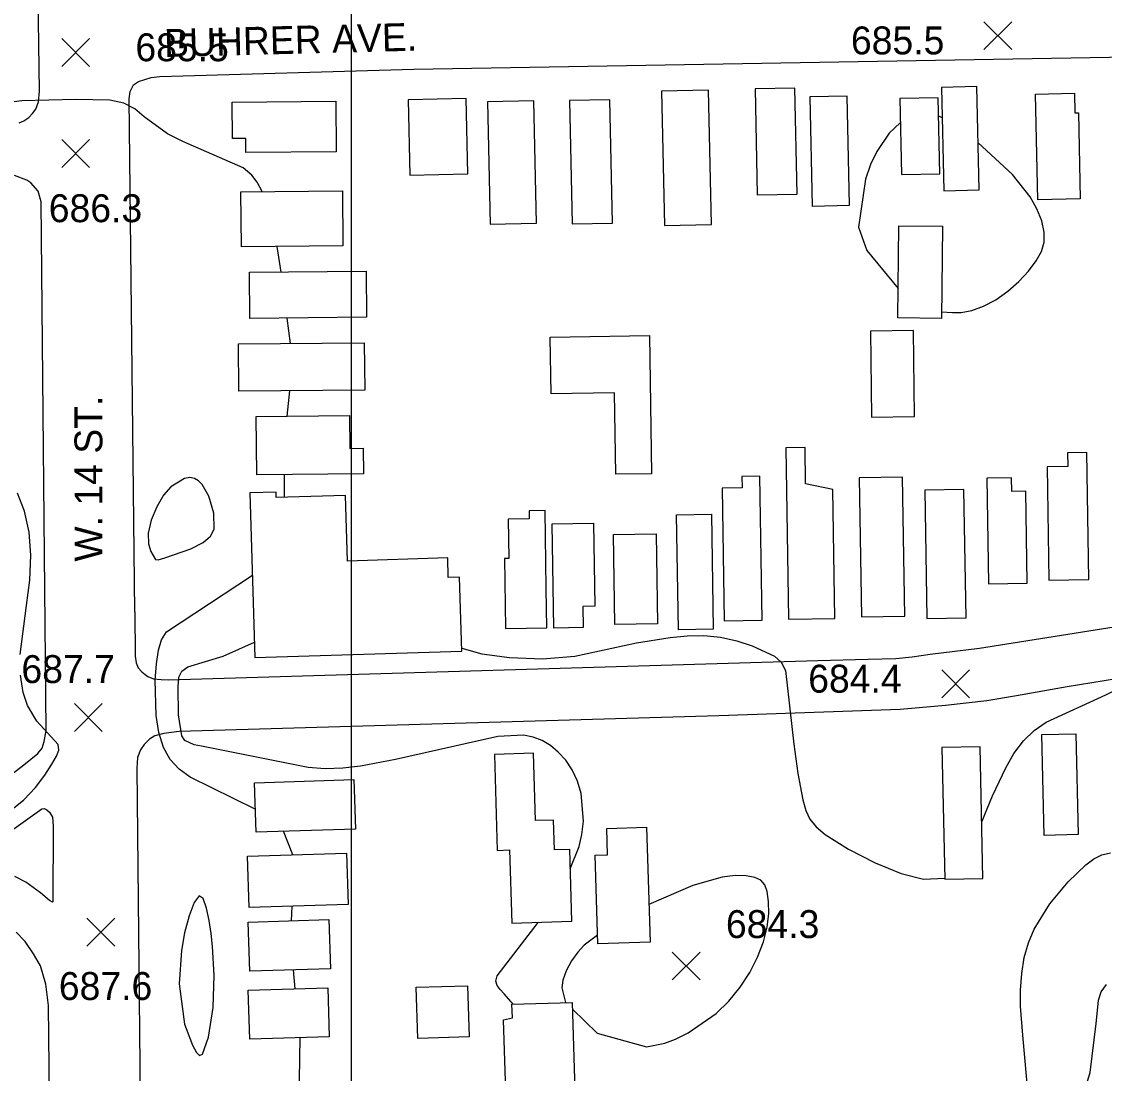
# Model space of a CAD drawing. Extents: x 79600 to 91800, y 75600 to 84400.
# Drawn here: x 86823 to 87405, y 77429 to 77994 of the extents above; entities that cross this region are included whole.
import ezdxf

# ---------------------------------------------------------------- set-up
doc = ezdxf.new("R2010")
doc.units = 0
for name, color, linetype in [('080-090$0$BLDG', 7, 'Continuous'), ('080-090$0$GRID', 7, 'Continuous'), ('080-090$0$INDEX', 7, 'Continuous'), ('080-090$0$INTER', 7, 'Continuous'), ('080-090$0$ROAD', 7, 'Continuous'), ('080-090$0$ROAD-NAME', 7, 'Continuous'), ('080-090$0$SPOTMARK', 7, 'Continuous'), ('080-090$0$SPOTS', 7, 'Continuous')]:
    doc.layers.add(name, color=color, linetype=linetype)

# ---------------------------------------------------------------- blocks, each defined once
blk = doc.blocks.new('080-090$0$SPOTS')
at = {"layer": '080-090$0$SPOTMARK'}
for p, q in [((-0.5, -0.5), (0.5, 0.5)), ((-0.5, 0.5), (0.5, -0.5))]:
    blk.add_line(p, q, dxfattribs=at)

msp = doc.modelspace()

# ---------------------------------------------------------------- linework, layer by layer
at = {"layer": '080-090$0$BLDG'}
for points in [[(87166.82, 77956.92), (87168.39, 77884.81), (87193.69, 77885.37), (87192.11, 77957.47)], [(87217.06, 77958.12), (87218.31, 77901.17), (87239.72, 77901.64), (87238.47, 77958.59)], [(87246.43, 77953.81), (87247.72, 77895.19), (87267.85, 77895.63), (87266.57, 77954.25)], [(87317.23, 77958.97), (87318.44, 77903.42), (87337.53, 77903.84), (87336.32, 77959.39)], [(87388.87, 77945.27), (87390.82, 77945.31), (87391.84, 77899), (87368.93, 77898.49), (87367.69, 77955.34), (87388.63, 77955.8)], [(86992.04, 77924.34), (86943.5, 77923.9), (86943.43, 77931.56), (86936.32, 77931.49), (86936.14, 77951.1), (86991.79, 77951.62)], [(87030.77, 77952.35), (87031.66, 77911.84), (87062.69, 77912.52), (87061.8, 77953.03)], [(87073.28, 77951.17), (87074.72, 77885.44), (87099.62, 77885.98), (87098.18, 77951.72)], [(87117.43, 77951.83), (87118.88, 77885.61), (87140.55, 77886.08), (87139.1, 77952.3)], [(87294.81, 77952.94), (87295.7, 77912.12), (87316.45, 77912.57), (87315.55, 77953.39)], [(86995.7, 77873.87), (86941.13, 77873.36), (86940.85, 77902.84), (86995.42, 77903.35)], [(87293.87, 77835.1), (87294.41, 77884.56), (87317.78, 77884.31), (87317.24, 77834.84)], [(87008.17, 77860.17), (87008.39, 77835.42), (86945.67, 77834.84), (86945.45, 77859.59)], [(87279.07, 77827.94), (87279.72, 77781.83), (87302.82, 77782.16), (87302.17, 77828.26)], [(87007.4, 77796.34), (86939.75, 77795.72), (86939.52, 77821.13), (87007.16, 77821.76)], [(87142.34, 77751.08), (87141.62, 77794.87), (87107.47, 77794.31), (87106.97, 77824.81), (87160.29, 77825.68), (87161.5, 77751.37)], [(86999.32, 77764.99), (87006.53, 77765.06), (87006.66, 77751.33), (86949.34, 77750.8), (86949.05, 77782.12), (86999.16, 77782.58)], [(87244.27, 77745.97), (87243.96, 77765.37), (87233.57, 77765.2), (87235.07, 77673.2), (87259.96, 77673.61), (87258.84, 77742.92)], [(87384.94, 77762.61), (87385.06, 77755.29), (87373.98, 77755.11), (87374.98, 77694.18), (87396.46, 77694.53), (87395.35, 77762.78)], [(87210.02, 77749.94), (87210.13, 77743.73), (87199.36, 77743.55), (87200.52, 77672.34), (87220.91, 77672.67), (87219.65, 77750.1)], [(87272.98, 77749.13), (87274.2, 77674.4), (87297.59, 77674.78), (87296.37, 77749.51)], [(87355.03, 77741.83), (87354.91, 77749.17), (87341.62, 77748.96), (87342.55, 77692.17), (87363.32, 77692.51), (87362.52, 77741.95)], [(87058.3, 77695.79), (87052.28, 77695.61), (87051.96, 77706.07), (86998.06, 77704.41), (86996.98, 77739.73), (86959.83, 77738.59), (86959.74, 77741.5), (86945.67, 77741.06), (86948.39, 77652.63), (87059.52, 77656.05)], [(87308.25, 77742.56), (87309.37, 77673.49), (87330.43, 77673.83), (87329.31, 77742.91)], [(87095.7, 77731.4), (87095.77, 77727.13), (87084.39, 77726.94), (87084.74, 77705.78), (87082.43, 77705.74), (87083.04, 77668.14), (87105.28, 77668.51), (87104.94, 77689.65), (87104.93, 77689.67), (87104.25, 77731.54)], [(87175.95, 77667.48), (87174.95, 77729.26), (87193.65, 77729.56), (87194.66, 77667.79)], [(87124.5, 77680.01), (87124.69, 77668.67), (87108.92, 77668.41), (87108.01, 77724.43), (87130.29, 77724.79), (87131.01, 77680.12)], [(87141.75, 77670.37), (87140.97, 77718.76), (87163.94, 77719.13), (87164.73, 77670.74)], [(87389.52, 77611.56), (87390.66, 77557.41), (87372.35, 77557.02), (87371.21, 77611.17)], [(87109.37, 77549.22), (87108.87, 77565.21), (87099.2, 77564.91), (87098.09, 77601.1), (87077.03, 77600.46), (87078.61, 77548.95), (87085.17, 77549.16), (87086.38, 77509.81), (87118.71, 77510.81), (87117.52, 77549.47)], [(87317.51, 77604.16), (87319, 77533.44), (87339.51, 77533.87), (87338.02, 77604.59)], [(87002.35, 77560.38), (86948.96, 77558.73), (86948.14, 77585.31), (87001.53, 77586.95)], [(87160.69, 77499.62), (87132.66, 77498.75), (87131.2, 77546.29), (87137.82, 77546.5), (87137.38, 77560.72), (87158.79, 77561.38)], [(86998.49, 77519.9), (86945.22, 77518.26), (86944.37, 77545.79), (86997.64, 77547.43)], [(86988.96, 77485.32), (86945.62, 77483.98), (86944.8, 77510.42), (86988.15, 77511.75)], [(86988.34, 77448.82), (86945.58, 77447.5), (86944.77, 77473.81), (86987.53, 77475.12)], [(87062.59, 77476.2), (87063.43, 77448.7), (87035.89, 77447.85), (87035.04, 77475.35)], [(87086.7, 77459), (87086.47, 77466.26), (87118.84, 77467.26), (87121.03, 77396.38), (87086.22, 77395.31), (87085.98, 77403.14), (87083.7, 77403.07), (87082.01, 77457.93)]]:
    msp.add_lwpolyline(points, close=True, dxfattribs=at)
at = {"layer": '080-090$0$GRID'}
msp.add_line((87000, 80000), (87000, 76000), dxfattribs=at)
at = {"layer": '080-090$0$INDEX'}
msp.add_lwpolyline([(87394.48, 77420.72), (87397.07, 77429.53), (87400.43, 77455.83), (87400.99, 77462.85), (87401.6, 77468.43), (87402.96, 77472.91), (87405.89, 77476.78)], dxfattribs=at)
at = {"layer": '080-090$0$INTER'}
for p, q in [((87317.59, 77942.56), (87315.77, 77943.55)), ((86962.46, 77859.75), (86960.37, 77873.54)), ((86967.42, 77821.39), (86965.71, 77835.02)), ((86965.76, 77782.27), (86967.22, 77795.97)), ((86964.32, 77738.72), (86964.35, 77750.94)), ((86968.75, 77546.54), (86963.73, 77559.19)), ((86968.11, 77511.14), (86968.43, 77518.98)), ((86969.97, 77474.58), (86969.07, 77484.71))]:
    msp.add_line(p, q, dxfattribs=at)
for points in [[(86952.32, 77902.95), (86949.57, 77908.09), (86946.7, 77911.82), (86942.08, 77915.71), (86909.61, 77929.9), (86901.42, 77934.06), (86888.83, 77943.16), (86883.77, 77947.37), (86877.97, 77950.49), (86870.51, 77952.08), (86852.2, 77952.48), (86823.08, 77951.8), (86776.05, 77945.64)], [(87295.09, 77939.85), (87289.14, 77934.41), (87282.48, 77924.57), (87279.13, 77917.53), (87276.39, 77909.63), (87272.73, 77883.77)], [(87317.28, 77838.38), (87323.17, 77837.91), (87327.86, 77838.04), (87333.54, 77839.06), (87339.85, 77841.37), (87346.43, 77844.88), (87352.89, 77849.38), (87358.87, 77854.61), (87364.07, 77860.19), (87368.2, 77865.69), (87371, 77870.82), (87372.42, 77875.85), (87372.45, 77881.22), (87371.1, 77887.21), (87368.51, 77893.62), (87364.87, 77900.1), (87355.41, 77912.14), (87336.98, 77929.2)], [(87272.73, 77883.77), (87277.16, 77871.32), (87294.05, 77850.91)], [(86822.17, 77654.24), (86825.69, 77680.45), (86827.49, 77694.2), (86828.02, 77707.51), (86827.08, 77719.95), (86824.64, 77731.15), (86820.79, 77740.85)], [(87338.87, 77564.19), (87344.66, 77578.25), (87351.76, 77593.31), (87356.18, 77600.96), (87361.24, 77607.81), (87366.99, 77613.38), (87373.5, 77617.92), (87405.51, 77632.54), (87412.64, 77636.19), (87418.36, 77640.48), (87422.22, 77646), (87425.63, 77660.75), (87428.42, 77668.07), (87433.87, 77674.13), (87485.17, 77701.91)], [(86948.58, 77571.08), (86913.56, 77588.23), (86907.59, 77592.5), (86902.86, 77597.73), (86899.3, 77604.27), (86896.84, 77612.3), (86895.36, 77621.41), (86894.78, 77640.47), (86895.44, 77649.19), (86896.59, 77656.54), (86898.25, 77662.09), (86900.92, 77666.41), (86947.03, 77696.75)], [(87059.47, 77657.61), (87070.27, 77654.62), (87085.14, 77652.57), (87102.91, 77651.83), (87120.19, 77653.28), (87153.45, 77660.47), (87171.49, 77663.35), (87180.53, 77664.24), (87189.53, 77664.44), (87198.5, 77663.6), (87207.37, 77661.56), (87215.58, 77658.79), (87227.6, 77653.25), (87231.12, 77650.12), (87233.38, 77645.52), (87237.99, 77605.96), (87240.15, 77590.33), (87242.71, 77576.03), (87244.3, 77570.44), (87246.54, 77565.75), (87249.91, 77561.53), (87254.71, 77557.43), (87267.36, 77549.5), (87281.54, 77542.28), (87295.61, 77536.57), (87307.57, 77533.43), (87318.99, 77534.04)], [(87117.84, 77539.05), (87122.51, 77550.95), (87124.07, 77557.39), (87124.87, 77564.59), (87123.71, 77579.42), (87121.68, 77586.17), (87118.82, 77592.2), (87115.34, 77597.43), (87111.39, 77601.79), (87107.12, 77605.3), (87102.63, 77607.96), (87097.95, 77609.79), (87092.71, 77610.77), (87078.91, 77610.14), (87023.9, 77597.86), (87005.07, 77594.21), (86995.6, 77593.12), (86986.19, 77592.79), (86976.95, 77593.44), (86919.67, 77604.87), (86915.7, 77605.68), (86910.68, 77607.99), (86909.09, 77610.51), (86907.31, 77621.86), (86907.07, 77636.91), (86907.58, 77641.96), (86909.13, 77645.24), (86912.41, 77647.52), (86931.4, 77653.33), (86948.14, 77660.77)], [(86816.94, 77570.14), (86824.26, 77576.12), (86830.46, 77582.79), (86835.46, 77589.43), (86839.25, 77595.22), (86841.82, 77599.54), (86843, 77602.85), (86842.61, 77605.82), (86831.28, 77618.31), (86826.18, 77626.71), (86823.94, 77633.85), (86822.41, 77643.11)], [(87363.99, 77415.66), (87360.91, 77449.69), (87359.74, 77465.23), (87359.74, 77473.87), (87360.34, 77482.72), (87361.7, 77491.29), (87363.94, 77499.22), (87367.04, 77506.58), (87375.45, 77520.15), (87385.38, 77532.06), (87394.77, 77541.15), (87399.13, 77544.33), (87403.38, 77546.46), (87407.97, 77547.6)], [(87158.85, 77443.28), (87168.55, 77445.29), (87174.3, 77447.41), (87181.2, 77450.82), (87196.15, 77461.22), (87203.01, 77467.92), (87209.1, 77475.36), (87214.28, 77483.31), (87218.47, 77491.53), (87221.59, 77499.75), (87223.59, 77507.69), (87224.44, 77515.07), (87224.36, 77521.55), (87223.59, 77526.76), (87222.29, 77530.46), (87220.21, 77532.9), (87216.97, 77534.43), (87212.31, 77535.31), (87206.37, 77535.43), (87199.35, 77534.57), (87183.67, 77530.05), (87160.07, 77519.94)], [(87087.15, 77466.28), (87082.25, 77471.85), (87080.2, 77474.22), (87078.57, 77476.35), (87077.85, 77478.61), (87078.53, 77481.51), (87100.53, 77510.25)], [(87132.51, 77503.45), (87125.3, 77497.96), (87121.86, 77494.27), (87118.5, 77489.5), (87115.67, 77484.24), (87113.81, 77479.2), (87113.2, 77474.99), (87115.26, 77467.15)], [(87118.96, 77463.6), (87132.31, 77450.77), (87158.85, 77443.28)], [(86959.62, 77368.68), (86968.71, 77397.6), (86972.2, 77414.16), (86972.71, 77448.34)]]:
    msp.add_lwpolyline(points, dxfattribs=at)
for points in [[(86900.04, 77706.15), (86913.87, 77711.07), (86920.5, 77714.33), (86924.6, 77717.77), (86926.44, 77721.47), (86926.22, 77730.2), (86923.63, 77739.24), (86920.1, 77745.57), (86918.09, 77747.57), (86915.9, 77748.85), (86913.41, 77749.31), (86910.47, 77748.84), (86903.2, 77744.37), (86899.3, 77739.79), (86895.6, 77733.47), (86892.66, 77726.31), (86891.09, 77719.42), (86891.26, 77713.76), (86892.5, 77709.51), (86894.89, 77705.24), (86896.48, 77705.11)], [(86911.39, 77453.18), (86914.93, 77444.27), (86916.93, 77440.36), (86918.65, 77438.62), (86920.19, 77439.38), (86923.35, 77448.47), (86925.99, 77464.58), (86926.55, 77481.83), (86925.66, 77497.33), (86924.87, 77504.32), (86923.8, 77511.21), (86922.42, 77517.95), (86920.65, 77522.99), (86918.42, 77524.42), (86915.75, 77520.95), (86912.99, 77513.75), (86910.58, 77504.59), (86908.87, 77495.05), (86907.69, 77477.21), (86910.51, 77455.61)]]:
    msp.add_lwpolyline(points, close=True, dxfattribs=at)
at = {"layer": '080-090$0$ROAD'}
for p, q in [((86832.7, 77956.98), (86828.17, 78265.72)), ((87033.69, 77968.67), (87769.3, 77981.63)), ((86897.25, 77964.84), (87033.69, 77968.67)), ((86881.31, 77956.82), (86883.06, 77960.41)), ((86883.06, 77960.41), (86885.75, 77962.16)), ((86885.75, 77962.16), (86892.64, 77964.25)), ((86892.64, 77964.25), (86897.25, 77964.84)), ((86832.06, 77951.17), (86832.7, 77956.98)), ((86880.8, 77952.78), (86881.31, 77956.82)), ((86830.75, 77947.32), (86832.06, 77951.17)), ((86883.79, 77677.09), (86880.8, 77952.78)), ((86824.15, 77940.91), (86826.94, 77942.8)), ((86826.94, 77942.8), (86828.92, 77944.99)), ((86828.92, 77944.99), (86830.75, 77947.32)), ((86821.64, 77939.98), (86824.15, 77940.91)), ((86825.87, 77909.03), (86819.12, 77911.63)), ((86828.07, 77907.61), (86825.87, 77909.03)), ((86831.88, 77903.26), (86828.07, 77907.61)), ((86833.59, 77897.42), (86831.88, 77903.26)), ((86836.28, 77613.35), (86833.59, 77897.42)), ((86883.79, 77677.09), (86884.1, 77653.22)), ((87621.03, 77675.2), (87384.75, 77636.87)), ((87337.76, 77657.58), (87433.55, 77672.77)), ((87311.17, 77654.4), (87337.76, 77657.58)), ((86884.1, 77653.22), (86884.58, 77649.72)), ((87250.81, 77650.99), (87277.9, 77651.65)), ((87277.9, 77651.65), (87292.7, 77652.02)), ((87292.7, 77652.02), (87301.51, 77652.94)), ((87301.51, 77652.94), (87311.17, 77654.4)), ((86884.58, 77649.72), (86885.64, 77647.04)), ((86885.64, 77647.04), (86887.68, 77644.91)), ((86901.68, 77640.55), (87250.81, 77650.99)), ((86887.68, 77644.91), (86889.46, 77643.47)), ((86889.46, 77643.47), (86890.83, 77642.32)), ((86890.83, 77642.32), (86893.88, 77641.14)), ((86893.88, 77641.14), (86897.92, 77640.77)), ((86897.92, 77640.77), (86901.68, 77640.55)), ((87384.75, 77636.87), (87357.57, 77632.02)), ((87341.6, 77629.31), (87319.49, 77626.72)), ((87357.57, 77632.02), (87341.6, 77629.31)), ((87295.02, 77624.61), (87197.54, 77621.18)), ((87319.49, 77626.72), (87295.02, 77624.61)), ((87197.54, 77621.18), (86907.63, 77612.79)), ((86835.22, 77607.41), (86836.28, 77613.35)), ((86899.37, 77611.71), (86894.6, 77610.42)), ((86907.63, 77612.79), (86899.37, 77611.71)), ((86834.06, 77603.83), (86835.22, 77607.41)), ((86888.91, 77605.8), (86886.9, 77602.92)), ((86891.77, 77608.67), (86888.91, 77605.8)), ((86894.6, 77610.42), (86891.77, 77608.67)), ((86824.23, 77594.98), (86831.66, 77600.96)), ((86831.66, 77600.96), (86834.06, 77603.83)), ((86886.9, 77602.92), (86885.27, 77598.76)), ((86763.94, 77548.78), (86824.23, 77594.98)), ((86885.27, 77598.76), (86885.01, 77593.19)), ((86885.01, 77593.19), (86887.81, 77290.28)), ((86831.32, 77569.53), (86833.84, 77571.29)), ((86833.84, 77571.29), (86835.22, 77571.41)), ((86835.22, 77571.41), (86836.6, 77570.69)), ((86836.6, 77570.69), (86838.1, 77569.56)), ((86809.48, 77553.94), (86831.32, 77569.53)), ((86838.1, 77569.56), (86839.58, 77566.77)), ((86839.58, 77566.77), (86839.93, 77561.92)), ((86839.93, 77561.92), (86839.72, 77521.35)), ((86825.34, 77531.82), (86819.43, 77534.95)), ((86833.14, 77526.16), (86825.34, 77531.82)), ((86837.93, 77522.07), (86833.14, 77526.16)), ((86839.71, 77521.07), (86837.93, 77522.07)), ((86839.72, 77521.35), (86839.71, 77521.07)), ((86824.85, 77499.97), (86820.08, 77505.03)), ((86829.45, 77493.26), (86824.85, 77499.97)), ((86833.23, 77486.83), (86829.45, 77493.26)), ((86835.99, 77477.09), (86833.23, 77486.83)), ((86837.48, 77465.57), (86835.99, 77477.09)), ((86838.47, 77368.07), (86837.48, 77465.57))]:
    msp.add_line(p, q, dxfattribs=at)

# ---------------------------------------------------------------- block references
at = {"layer": '080-090$0$SPOTMARK', "xscale": 15, "yscale": 15}
for p in [(87347.47, 77986.75), (86852.07, 77977.7), (86852.07, 77923.41), (87324.85, 77638.38), (86858.86, 77620.28), (86865.64, 77504.92), (87180.08, 77486.82)]:
    msp.add_blockref('080-090$0$SPOTS', p, dxfattribs=at)

# ---------------------------------------------------------------- texts
at = {"layer": '080-090$0$ROAD-NAME'}
for s, rotation, p in [('BUHRER AVE.', 1.44972, (86899.76, 77975.26)), ('W. 14 ST.', 90.04745, (86866.48, 77704.13))]:
    msp.add_text(s, height=15, rotation=rotation, dxfattribs=at).set_placement(p)
at = {"layer": '080-090$0$SPOTS'}
for s, p in [('685.5', (87268.6, 77976.7)), ('685.5', (86884.16, 77973.02)), ('686.3', (86837.62, 77886.53)), ('687.7', (86822.93, 77638.86)), ('684.4', (87245.64, 77633.7)), ('684.3', (87201.43, 77501.82)), ('687.6', (86843.02, 77468.54))]:
    msp.add_text(s, height=15, dxfattribs=at).set_placement(p)

doc.saveas('drawing.dxf')
